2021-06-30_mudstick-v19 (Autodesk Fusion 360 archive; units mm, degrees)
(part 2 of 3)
sketch "Sketch19" plane through (2.9, 0, 0) normal (-1, 0, 0) x axis (0, -1, 0)
  line L1 (27.1, 161.9153) -> (13.5, 161.9153)
  line L2 (30.1, 117.9153) -> (30.1, 158.9153)
  line L3 (10.5, 114.9153) -> (27.1, 114.9153)
  line L4 (10.5, 114.75) -> (10.5, 114.9153)
  line L5 (10.1, 114.75) -> (10.5, 114.75)
  line L6 (10.1, 2.6653) -> (10.1, 114.75)
  line L7 (10.5, 2.6653) -> (10.1, 2.6653)
  line L8 (10.5, -11) -> (10.5, 2.6653)
  line L9 (27.35, -11) -> (10.5, -11)
  line L10 (27.35, -7.85) -> (27.35, -11)
  line L11 (52.65, -7.85) -> (27.35, -7.85)
  line L12 (52.65, -11) -> (52.65, -7.85)
  line L13 (73, -11) -> (52.65, -11)
  line L14 (73, 234.2448) -> (73, -11)
  line L15 (52.65, 234.2448) -> (73, 234.2448)
  line L16 (52.65, 231.0948) -> (52.65, 234.2448)
  line L17 (27.35, 231.0948) -> (52.65, 231.0948)
  line L18 (27.35, 234.2448) -> (27.35, 231.0948)
  line L19 (4, 234.2448) -> (27.35, 234.2448)
  line L20 (4, 182.2448) -> (4, 234.2448)
  line L21 (7.5, 179.2448) -> (7, 179.2448)
  line L22 (10.5, 164.9153) -> (10.5, 176.2448)
  line L23 (105.1, 16.4153) -> (85.1, 16.4153)
  line L24 (105.1, 36.4153) -> (105.1, 16.4153)
  line L25 (85.1, 36.4153) -> (105.1, 36.4153)
  line L26 (85.1, 16.4153) -> (85.1, 36.4153)
  line L27 (25, 7.4153) -> (65, 7.4153)
  line L28 (105.1, 26.4153) -> (85.1, 26.4153)
  arc A1 centre (13.5, 164.9153) radius 3 clockwise from (13.5, 161.9153) to (10.5, 164.9153)
  arc A2 centre (27.1, 158.9153) radius 3 clockwise from (27.1, 161.9153) to (30.1, 158.9153)
  arc A3 centre (27.1, 117.9153) radius 3 clockwise from (30.1, 117.9153) to (27.1, 114.9153)
  arc A4 centre (7, 182.2448) radius 3 clockwise from (7, 179.2448) to (4, 182.2448)
  arc A5 centre (7.5, 176.2448) radius 3 clockwise from (7.5, 179.2448) to (10.5, 176.2448)
  circle C1 centre (12, 224.2448) radius 2.125
  circle C2 centre (16.5, -5) radius 2.125
  circle C3 centre (63.5, -5) radius 2.125
  circle C4 centre (68, 224.2448) radius 2.125
  circle C5 centre (65, 7.4153) radius 1.65
  circle C6 centre (25, 7.4153) radius 1.65
  circle C7 centre (65, 45.4153) radius 1.65
  circle C8 centre (25, 45.4153) radius 1.65
  point P43 (65, 7.4153)
  point P45 (65, 7.4153)
  point P44 (25, 7.4153)
  point P46 (25, 7.4153)
  point P47 (85.1, 26.4153)
  point P48 (105.1, 26.4153)
  point P40 (105.1, 36.4153)
  point P41 (85.1, 36.4153)
  point P42 (0.1, 2.4153)
  horizontal L23
  vertical L24
  horizontal L25
  vertical L26
  equal L25 L26
  coincident P43 P45
  coincident P44 P46
  horizontal L27
  equal C5 C6
  midpoint L26 P47
  midpoint L24 P48
  symmetric C5 L28 C7
  symmetric C6 L28 C8
  dimension "d552" distance P40 P41 = 20
  dimension "d553" distance L23 P42 = 14
  dimension "d554" diameter C5 = 3.3
  dimension "d555" distance L23 L27 = 9
  dimension "d556" distance L14 P43 = 8
  dimension "d557" distance P45 P46 = 40
  dimension "d558" distance L26 P42 = 85
extrude "Extrude33" cut sketch "Sketch19" profile of C5 C6 C7 C8 to an object
fillet "Fillet23" radius 2
offset_faces "OffsetFaces1" distance -0.25
fillet "Fillet24" radius 2
fillet "Fillet25" radius 2
fillet "Fillet26" radius 3
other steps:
joint_origin "JointOrigin1"
joint_origin "JointOrigin2"
joint_origin "JointOrigin3"
named bodies: "Home Plate", "Canister", "Nozzle", "Drive", "Drive Cap", "Drive Housing", "Outer Plunger", "Ball Screw", "Inner Plunger", "Lower Cup", "West Wing", "East Wing", "Drive Housing (1)", "Handle"

design "PULL OUT DOWEL 6x16 97355A292"
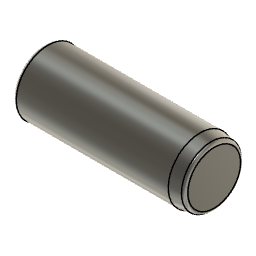
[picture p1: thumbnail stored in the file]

design "BHCS M4 x 25 92095A197"
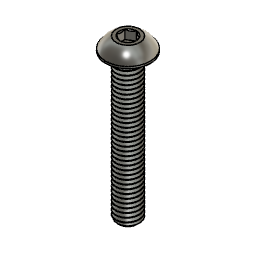
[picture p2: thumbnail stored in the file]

design "BHCS M4x10 92095A190"
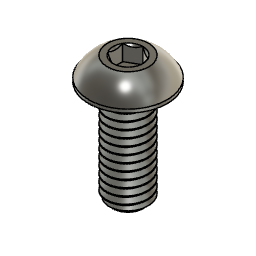
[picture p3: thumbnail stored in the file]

design "Mudstick Plate" references "Hotplate Pogo Drop", "BHCS M4 x 25 92095A197", "BHCS M4x10 92095A190", "PULL OUT DOWEL 6x16 97355A292"
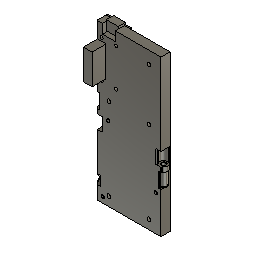
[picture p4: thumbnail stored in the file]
parameter "t_sheet_MAIN" = 7.9375 (= "5 / 16 * 1")
parameter "extrusion_w" = 20
parameter "extrusion_h" = 60
parameter "r_cutoutTool" = 2.05 (= "4.1 mm / 2")
parameter "od_bearings" = 13
parameter "id_bearings" = 4
parameter "t_bearings" = 5
parameter "preload" = 0.15
parameter "hw_m3_thru" = 3.5
parameter "hw_m3_thread" = 2.5
parameter "hw_m3_head" = 5.5
parameter "hw_m3_headheight" = 3
parameter "hw_m3_flathead" = 6
parameter "hw_m3_buttonhead" = 5.7
parameter "hw_m3_washer" = 7
parameter "hw_m3hex_d" = 5.5
parameter "hw_m3hex_t" = 4
parameter "hw_m3i_d" = 5.4
parameter "hw_m3i_l" = 3.8
parameter "hw_m3ichamfer" = 0.95 (= "( hw_m3i_d - hw_m3_thru ) / 2")
parameter "hw_m4_thru" = 4.25
parameter "hw_m4_head" = 7
parameter "hw_m4_headheight" = 4
parameter "hw_m4hex_d" = 7
parameter "hw_m4hex_t" = 5.2
parameter "hw_m4i_d" = 6
parameter "hw_m4i_l" = 4.8
parameter "hw_m4ichamfer" = 0.875 (= "( hw_m4i_d - hw_m4_thru ) / 2")
parameter "hw_m5_thread" = 4.2
parameter "hw_m5_head" = 8.5
parameter "hw_m5_washer" = 10
parameter "hw_m5_thru" = 5.25
parameter "hw_m6_thru" = 6.5
parameter "hw_m6_head" = 10
parameter "hw_m6_flathead" = 12
parameter "hw_m6_buttonhead" = 10.5
parameter "hw_m6_washer" = 12
parameter "p_belt" = 1.4
parameter "w_belt" = 10
parameter "t_belt" = 1.4
parameter "belt_pdo_toothside" = 1.15
parameter "belt_pdo_backside" = 0.25
parameter "t_m4_washer" = 0.85
parameter "flex_t" = 2.54
parameter "flex_l" = 5
parameter "t_motor_plates" = 6 comment "5/16 Phenolic"
parameter "swap_center_distance" = 40
parameter "pd_swap_drive" = 57.2958 (= "( nt_swap_drive * 2 / PI ) * 1 mm")
parameter "pd_swap_pinion" = 10.1859 (= "( nt_swap_pinion * 2 / PI ) * 1 mm")
parameter "od_mintool" = 2.1
parameter "t_sheet_THIN" = 5
parameter "c2c_spanners" = 14
parameter "c2c_height_pts" = 75
parameter "d954" = 1.7
parameter "d1221" = 5
parameter "d1747" = 9
parameter "d1748" = 5.5 (= "t_sheet_THIN + 0.5 mm")
parameter "d1761" = 2
parameter "d1917" = 5
sketch "Plan" plane through (0, 0, 0) normal (0, 0, 1) x axis (1, 0, 0)
  line L1 (-35, -5) -> (35, -5)
  line L2 (35, 5) -> (-35, 5)
  line L3 (35, -5) -> (35, 5)
  line L4 (-32.8378, -7.9826) -> (-38.2756, -10.5183)
  line L5 (-39.5997, 6.5183) -> (-32.8378, -7.9826)
  line L6 (-45.0375, 3.9826) -> (-39.5997, 6.5183)
  line L7 (-38.2756, -10.5183) -> (-45.0375, 3.9826)
  line L8 (-35.5567, -9.2505) -> (-42.3186, 5.2505)
  line L9 (-35, -3.8) -> (-35.5, -3.8)
  line L10 (-35, 3.8) -> (-35.5, 3.8)
  line L11 (-35.5, -3.8) -> (-35.5, 3.8)
  line L12 (-35.5, 0) -> (-35, 0)
  line L13 (0, -5) -> (0, 5)
  line L14 (35, 0) -> (-35, 0)
  line L15 (-33.25, 3) -> (-35, 3)
  line L16 (-30.25, -5) -> (-30.25, 0)
  line L17 (-32.75, -20) -> (-32.75, -12.9033)
  line L18 (-47.0948, -20) -> (-32.75, -20)
  line L19 (-58.5, 4.4586) -> (-47.0948, -20)
  line L20 (-58.5, 18.5) -> (-58.5, 4.4586)
  line L21 (-36.5156, 6.5) -> (0, 6.5)
  line L22 (-32.75, -12.9033) -> (-40.8544, 4.4768)
  line L23 (40, -5.1) -> (-40, -5.1)
  line L24 (40, -17.8) -> (40, -5.1)
  line L25 (-40, -17.8) -> (40, -17.8)
  line L26 (-40, -5.1) -> (-40, -17.8)
  line L27 (0, -17.8) -> (0, -5.1)
  line L28 (45, 18.5) -> (0, 18.5)
  line L29 (37.0839, 1.7621) -> (34.359, -5.7245)
  line L30 (39.0574, -7.4346) -> (34.359, -5.7245)
  line L31 (45.3388, -0.0273) -> (39.0574, -7.4346)
  line L32 (40, 4.5) -> (40, 24.5)
  line L33 (43.9547, 25.1) -> (46.9208, 5.55)
  line L34 (45, 4.5) -> (45, 18.5)
  line L35 (45, 4.5) -> (40, 4.5)
  line L36 (36, 6.5) -> (0, 6.5)
  line L37 (36, 4.5) -> (36, 6.5)
  line L38 (45, 0.5) -> (45, 4.5)
  line L39 (40, 0.5) -> (45, 0.5)
  line L40 (-58.5, 18.5) -> (0, 18.5)
  line L41 (0, 18.5) -> (0, 6.5)
  line L42 (-36.5156, 6.5) -> (-40.8544, 4.4768)
  line L43 (-35, 6.5) -> (-36.5156, 6.5)
  line L44 (-35, 18.5) -> (-35, 6.5)
  line L45 (35, 18.5) -> (35, 6.5)
  line L46 (40, 0.5) -> (36, 0.5)
  line L47 (40, 7.6754) -> (42.75, 6.0877)
  line L48 (37.25, 6.0877) -> (40, 7.6754)
  line L49 (37.25, 2.9123) -> (37.25, 6.0877)
  line L50 (40, 1.3246) -> (37.25, 2.9123)
  line L51 (42.75, 2.9123) -> (40, 1.3246)
  line L52 (42.75, 6.0877) -> (42.75, 2.9123)
  line L53 (43.1754, 24.5) -> (41.5877, 21.75)
  line L54 (41.5877, 27.25) -> (43.1754, 24.5)
  line L55 (38.4123, 27.25) -> (41.5877, 27.25)
  line L56 (36.8246, 24.5) -> (38.4123, 27.25)
  line L57 (38.4123, 21.75) -> (36.8246, 24.5)
  line L58 (41.5877, 21.75) -> (38.4123, 21.75)
  line L59 (36, 24.5) -> (36, 6.5)
  line L60 (36, 4.5) -> (36, 0.5)
  line L61 (20.3431, 18.5) -> (32.3431, 6.5)
  line L62 (-15, 11.5) -> (-35, 11.5)
  line L63 (-15, 18.5) -> (-15, 11.5)
  line L64 (-35, 2.4367) -> (-35, -5)
  line L65 (-35, 5) -> (-35, 3)
  line L66 (-33.25, -5) -> (-33.25, -3)
  line L67 (33.25, 3) -> (35, 3)
  line L68 (30.25, -5) -> (30.25, 0)
  line L69 (33.25, -5) -> (33.25, -3)
  line L70 (-35, 3) -> (-35, 2.4367)
  arc A1 centre (-32.1029, 0) radius 5.0971 clockwise from (-35.5, -3.8) to (-35.5, 3.8)
  circle C1 centre (-33.25, 0) radius 3
  circle C2 centre (33.25, 0) radius 3
  circle C3 centre (40, 4.5) radius 1.625
  circle C4 centre (40, 24.5) radius 1.625
  circle C5 centre (40, 24.5) radius 4
  circle C6 centre (40, 4.5) radius 4
  arc A2 centre (40, 4.5) radius 7 clockwise from (46.9208, 5.55) to (45.3388, -0.0273)
  circle C7 centre (-33.25, 0) radius 4.25
  circle C8 centre (-33.25, 0) radius 2.125
  circle C9 centre (33.25, 0) radius 3
  circle C10 centre (33.25, 0) radius 2.125
  circle C11 centre (33.25, 0) radius 4.25
  point P10 (-42.3186, 5.2505)
  point P11 (-35.5567, -9.2505)
  point P15 (-35, -3.8)
  point P16 (-35, 3.8)
  point P14 (-35.5, -3.8)
  point P17 (-35.5, -3.8)
  point P19 (-35.5, 0)
  point P20 (-37.2, 0)
  point P21 (0, 5)
  point P22 (0, -5)
  point P1 (0, 0)
  point P24 (35, 0)
  point P23 (-33.25, 0)
  point P25 (-35, 3)
  point P26 (-30.25, -5)
  point P27 (-38.9377, -2)
  point P41 (0, -5.1)
  point P42 (0, -17.8)
  point P52 (40, 24.5)
  point P54 (40, 24.5)
  point P49 (37.0839, 1.7621)
  point P58 (45.3388, -0.0273)
  point P51 (45.3388, -0.0273)
  point P60 (43.9547, 25.1)
  point P61 (40, 28.5)
  point P56 (40, 4.5)
  point P63 (40, 4.5)
  point P62 (45, 4.5)
  point P64 (45, 4.5)
  point P66 (36, 4.5)
  point P68 (40, 0.5)
  point P36 (0, 6.5)
  point P45 (0, 6.5)
  point P33 (-58.5, 18.5)
  point P69 (-58.5, 18.5)
  point P34 (-36.5156, 6.5)
  point P70 (-36.5156, 6.5)
  point P28 (-32.75, -12.9033)
  point P29 (-32.75, -12.9033)
  point P72 (-35, 18.5)
  point P4 (-35, 5)
  point P73 (35, 6.5)
  point P74 (35, 18.5)
  point P5 (35, 5)
  point P76 (40, 0.5)
  point P47 (40, 4.5)
  point P83 (40, 4.5)
  point P90 (40, 24.5)
  point P57 (40, 4.5)
  point P55 (40, 4.5)
  point P91 (36, 24.5)
  point P92 (36, 4.5)
  point P93 (32.3431, 6.5)
  point P94 (20.3431, 18.5)
  point P95 (-35, 11.5)
  point P97 (-15, 18.5)
  point P100 (-35, 2.4367)
  point P18 (-35, 0)
  point P101 (-33.25, 3)
  point P102 (-33.25, -3)
  point P103 (-33.25, -5)
  point P98 (-33.25, 0)
  point P104 (-30.25, 0)
  point P107 (35, 3)
  point P111 (30.25, -5)
  point P108 (33.25, 3)
  point P112 (33.25, -3)
  point P113 (33.25, -5)
  point P110 (30.25, 0)
  point P3 (-35, -5)
  point P6 (-38.2756, -10.5183)
  point P9 (-45.0375, 3.9826)
  point P8 (-39.5997, 6.5183)
  point P13 (-35.5, 3.8)
  point P37 (-40, -5.1)
  point P38 (40, -5.1)
  point P44 (33.25, 0)
  point P48 (34.359, -5.7245)
  point P50 (39.0574, -7.4346)
  point P53 (40, 24.5)
  point P67 (45, 0.5)
  point P43 (0, 18.5)
  point P79 (37.25, 6.0877)
  point P86 (41.5877, 27.25)
  point P96 (-15, 11.5)
  point P71 (-35, 6.5)
  horizontal L1
  vertical L64
  horizontal L2
  vertical L3
  perpendicular L4 L5
  parallel L4 L6
  parallel L5 L7
  midpoint L6 P10
  midpoint L4 P11
  coincident P15 L64
  perpendicular L9 L64
  coincident P16 L64
  perpendicular L10 L64
  perpendicular L10 L11
  coincident P14 P17
  perpendicular L12 L64
  midpoint L11 P19
  midpoint A1 P20
  midpoint L2 P21
  midpoint L1 P22
  midpoint P1 L13
  midpoint L3 P24
  coincident P23 L14
  coincident P25 L64
  perpendicular L15 L64
  coincident L1 P26
  perpendicular L1 L16
  midpoint L8 P27
  vertical L17
  perpendicular L17 L18
  vertical L20
  horizontal L23
  vertical L24
  horizontal L25
  vertical L26
  midpoint L23 P41
  midpoint L25 P42
  coincident P1 L27
  horizontal L21
  symmetric L13 C1 C2
  perpendicular L29 L30
  concentric C4 C5
  coincident P52 P54
  tangent C2 L29
  vertical L32
  coincident P49 C6
  coincident L31 P58
  coincident P51 P58
  tangent L31 A2
  coincident C5 P60
  tangent C5 L33
  tangent A2 L33
  coincident C5 P61
  coincident L32 P61
  perpendicular L28 L34
  coincident P56 P63
  perpendicular L32 L35
  coincident P62 P64
  perpendicular L36 L37
  coincident C6 P66
  coincident L35 P66
  perpendicular L35 L38
  perpendicular L34 L39
  coincident C6 P68
  coincident L32 P68
  coincident P36 P45
  coincident P33 P69
  perpendicular L28 L41
  coincident P1 L41
  horizontal L28
  horizontal L36
  horizontal L40
  perpendicular L5 L42
  coincident P34 P70
  parallel L8 L22
  coincident P28 P29
  parallel L8 L19
  parallel L21 L43
  coincident L40 P72
  perpendicular L40 L44
  coincident P4 L44
  coincident L36 P73
  coincident L28 P74
  perpendicular L28 L45
  coincident P5 L45
  equal C5 C6
  perpendicular L37 L46
  coincident P68 P76
  coincident P47 P83
  vertical L52
  coincident P52 P90
  horizontal L58
  coincident P57 P83
  coincident P55 P57
  coincident P47 P56
  coincident C5 P91
  perpendicular L46 L60
  coincident P66 P92
  coincident L36 P93
  coincident L28 P94
  tangent C6 L61
  coincident L44 P95
  perpendicular L41 L62
  coincident L40 P97
  perpendicular L40 L63
  tangent L5 C1
  concentric C1 C7
  concentric C1 C8
  coincident C1 P100
  collinear L64 L65
  coincident P18 L64
  coincident C1 P101
  coincident C1 P102
  coincident L1 P103
  perpendicular L1 L66
  coincident P98 L66
  coincident C1 P104
  symmetric L13 C1 C9
  symmetric L13 P25 P107
  symmetric L13 P26 P111
  symmetric L13 C7 C11
  symmetric L13 C8 C10
  symmetric L13 P101 P108
  symmetric L13 P102 P112
  symmetric L13 P103 P113
  symmetric L13 P104 P110
  dimension "d1706" distance P3 P4 = 10
  dimension "d1707" distance P6 P9 = 16
  dimension "d1708" distance P8 P9 = 6
  dimension "d1709" distance P13 P17 = 7.6
  dimension "d1710" distance P20 L64 = 2.2
  dimension "d1711" distance P13 P16 = 0.5
  dimension "d1712" distance P1 L64 = 35
  dimension "d1713" diameter C1 = 6
  dimension "d1714" distance P23 L64 = 1.75
  dimension "d1715" distance P23 L16 = 3 (= "d1713 / 2")
  dimension "d1716" distance P23 L15 = 3 (= "d1715")
  dimension "d1717" angle L8 L64 = 25
  dimension "d1723" distance L14 P27 = 2
  dimension "d1731" distance L17 L64 = 2.25
  dimension "d1732" distance L14 L18 = 20
  dimension "d1734" distance P27 L22 = 1
  dimension "d1763" distance P37 P38 = 80
  dimension "d1764" distance P41 P42 = 12.7
  dimension "d1765" distance L1 L23 = 0.1
  dimension "d1796" diameter C3 = 3.25
  dimension "d1799" distance L3 P47 = 5
  dimension "d1800" diameter C4 = 3.25
  dimension "d1802" angle L3 L29 = 20
  dimension "d1803" distance P44 L30 = 5
  dimension "d1804" distance P48 P50 = 5
  dimension "d1805" = 8.2688
  dimension "d1806" distance P47 P53 = 20
  dimension "d1808" = 1.5
  dimension "d1809" diameter C6 = 8
  dimension "d1810" distance P44 P47 = 4.5
  dimension "d1811" radius A2 = 7
  dimension "d1827" distance P67 P68 = 5
  dimension "d1955" distance L14 L21 = 6.5
  dimension "d1988" distance P36 P43 = 12
  dimension "d1989" distance P4 L42 = 2
  dimension "d1990" distance P27 L19 = 15
  dimension "d2035" distance P79 L52 = 5.5
  dimension "d2036" distance P86 L58 = 5.5
  dimension "d2063" angle L32 L61 = 45
  dimension "d2100" distance P95 P96 = 20
  dimension "d2126" distance P71 L62 = 5
  dimension "d2129" diameter C7 = 8.5
  dimension "d2130" diameter C8 = 4.25
  dimension "d2131" radius A1 = 5.0971
  dimension "d2236" distance L20 P72 = 23.5
  dimension "d523" OffsetX = 0
  dimension "d524" OffsetY = 0
  dimension "d525" OffsetZ = 0
  dimension "d526" AngleZ = 0
  dimension "d567" OffsetX = 0
  dimension "d568" OffsetY = 0
  dimension "d569" OffsetZ = 0
  dimension "d570" AngleZ = 0
  dimension "d1892" alignAngle = 180
  dimension "d1893" alignOffsetX = 0
  dimension "d1894" alignOffsetY = 0
  dimension "d1895" alignOffsetZ = 1
  dimension "d1896" radius = 1.05 (= "od_mintool / 2")
  dimension "d1897" distance = 1.05 (= "d1896")
  dimension "d1898" radius = 1.05 (= "od_mintool / 2")
  dimension "d1899" distance = 1.05 (= "d1898")
  dimension "d1900" distance = 17
  dimension "d1901" distance = 15
  dimension "d1916" distance = 10
  dimension "d1918" distance = 5
  dimension "d1919" distance = 25
  dimension "d1923" angle = 45
  dimension "d1924" diameter = 2.1 (= "od_mintool")
  dimension "d1925" diameter = 2.1 (= "od_mintool")
  dimension "d1926" diameter = 2.1 (= "od_mintool")
  dimension "d1932" angle = 45
  dimension "d1933" diameter = 2.1 (= "od_mintool")
  dimension "d1934" diameter = 2.1 (= "od_mintool")
  dimension "d1966" distance = 67
  dimension "d1967" distance = 33
  dimension "d1968" diameter = 2.5
  dimension "d1969" distance = 4
  dimension "d1970" distance = 29
  dimension "d1971" distance = 34
  dimension "d1972" distance = 54
  dimension "d1973" distance = 4
  dimension "d1974" distance = 3
  dimension "d1975" distance = 3
  dimension "d1976" distance = 5
  dimension "d1977" distance = 5
  dimension "d1978" distance = 1
  dimension "d1979" distance = 1
  dimension "d1980" distance = 10
  dimension "d1981" distance = 10
  dimension "d1982" distance = 6
  dimension "d1597" distance = 1.6
  dimension "d1598" distance = 67
  dimension "d1599" diameter = 4.25
  dimension "d1600" diameter = 3.3
  dimension "d1601" distance = 1
  dimension "d1602" distance = 1
  dimension "d1603" distance = 0.5
  dimension "d1604" distance = 12
  dimension "d1605" distance = 0.25
  dimension "d1606" distance = 0.25
  dimension "d1607" distance = 1
  dimension "d1608" distance = 8
  dimension "d1609" distance = 4.5
  dimension "d1610" distance = 4.5
  dimension "d1612" TaperAngle = 0
  dimension "d1613" AlongDistance = -53 (= "-20 mm - 33 mm")
  dimension "d1614" TaperAngle = 0
  dimension "d1615" ProfileOffset = 0.1
  dimension "d1616" Side1Offset = 0
  dimension "d1617" TaperAngle = 0
  dimension "d1618" leftDistance = 1
  dimension "d1619" distance = 67
  dimension "d1620" distance = 33
  dimension "d1621" distance = 0.5
  dimension "d1622" distance = 24.5
  dimension "d1623" diameter = 2.5
  dimension "d1624" distance = 4
  dimension "d1625" distance = 34
  dimension "d1626" distance = 54
  dimension "d1627" distance = 4
  dimension "d1628" distance = 29
  dimension "d1631" distance = 1
  dimension "d1633" distance = 3
  dimension "d1634" distance = 2.44 (= "d1643")
  dimension "d1635" diameter = 4
  dimension "d1636" distance = 15
  dimension "d1637" distance = 3
  dimension "d1638" distance = 15
  dimension "d1639" distance = 2
  dimension "d1640" Side1Offset = 0
  dimension "d1641" TaperAngle = 0
  dimension "d1642" distance = 2.44
  dimension "d1643" distance = 2.44
  dimension "d1644" AlongDistance = -16
  dimension "d1645" TaperAngle = 0
  dimension "d1647" Radius = 1
  dimension "d1649" Radius = 1
  dimension "d1651" Radius = 5
  dimension "d1653" Radius = 1
  dimension "d1654" diameter = 12
  dimension "d1655" Side1Offset = 0
  dimension "d1656" TaperAngle = 0
  dimension "d1658" Radius = 2
  dimension "d1659" distance = 20
  dimension "d1660" distance = 5
  dimension "d1661" distance = 5
  dimension "d981" distance = 15 (= "( 30 / 2 ) * 1 mm")
  dimension "d982" distance = 8
  dimension "d983" distance = 1.5
  dimension "d984" distance = 0.3
  dimension "d985" distance = 4
  dimension "d987" distance = 1
  dimension "d988" distance = 7.5
  dimension "d989" distance = 5
  dimension "d990" distance = 0.5
  dimension "d991" AlongAngle = 60
  dimension "d992" AgainstAngle = 60
  dimension "d993" distance = 4
  dimension "d994" angle = 60
  dimension "d995" angle = 60 (= "d994")
  dimension "d1004" diameter = 6.5
  dimension "d1005" distance = 1.5
  dimension "d1006" AlongDistance = -10
  dimension "d1007" TaperAngle = 0
  dimension "d1008" Side1Offset = 0
  dimension "d1009" TaperAngle = 0
  dimension "d1010" ProfileOffset = 0
  dimension "d1011" AlongDistance = -0.5
  dimension "d1012" TaperAngle = 0
  dimension "d1013" AlongDistance = 2.5
  dimension "d1014" TaperAngle = 0
  dimension "d1015" leftDistance = 0.25
  dimension "d1017" Radius = 1
  dimension "d1019" TotalAngle = 360
  dimension "d1020" ProfileOffset = 0
  dimension "d1021" Side1Offset = 0
  dimension "d1022" TaperAngle = 0
  dimension "d1028" angle = 25
  dimension "d1029" ProfileOffset = 0
  dimension "d1030" Side1Offset = 0
  dimension "d1031" TaperAngle = 0
  dimension "d1032" ProfileOffset = 0
  dimension "d1034" TaperAngle = 0
  dimension "d1035" Side1Offset = 0
  dimension "d1036" distance = 3
  dimension "d1037" leftDistance = 3
  dimension "d1038" rightDistance = 17.25
  dimension "d1039" Side1Offset = 0
  dimension "d1040" TaperAngle = 0
  dimension "d1042" TotalAngle = 360
  dimension "d1043" Side1Offset = 0
  dimension "d1044" TaperAngle = 2
  dimension "d1045" angle = 1
  dimension "d1047" Side1Offset = 0
  dimension "d1048" TaperAngle = 0
  dimension "d1049" distance = -1 (= "0 mm - 1 mm")
  dimension "d1051" TotalAngle = 360
  dimension "d1053" angle = 43.731
  dimension "d1054" angle = 28 (= "d1055 - d1056")
  dimension "d1055" angle = 50 (= "d1028 * 2")
  dimension "d1056" angle = 22
  dimension "d1058" Radius = 2
  dimension "d1060" Radius = 2
  dimension "d1061" alignAngle = 0
  dimension "d1062" alignOffsetX = 0
  dimension "d1063" alignOffsetY = 0
  dimension "d1064" alignOffsetZ = 0
  dimension "d1082" distance = 0.8
  dimension "d1084" distance = 0.8
  dimension "d1085" distance = 1.2
  dimension "d1086" distance = 1.2
  dimension "d1087" distance = 0.1
  dimension "d1093" Radius = 0.5
  dimension "d1095" Radius = 0.5
  dimension "d1097" Radius = 2
  dimension "d1103" distance = 1.3
  dimension "d1105" TotalAngle = 360
  dimension "d1106" distance = 2.75 (= "hw_m3hex_d / 2")
  dimension "d1107" distance = 1.75 (= "hw_m3_thru / 2")
  dimension "d1108" angle = 45
  dimension "d1109" distance = 3.6
  dimension "d1110" distance = 20
  dimension "d1111" distance = 1.7
  dimension "d1112" AlongAngle = 360
  dimension "d1113" Side1Offset = 0
  dimension "d1114" TaperAngle = 0
  dimension "d1116" TotalAngle = 360
  dimension "d1118" Radius = 2
  dimension "d1120" distance = 3.175 (= "1 / 8 * 1")
  dimension "d1121" radius = 12
  dimension "d1123" radius = 6.5
  dimension "d1124" angle = 60
  dimension "d1126" distance = 2.8797 (= "13 / 64 * 1  / 2 + 0.3 mm")
  dimension "d1127" distance = 9.5563 (= "7 / 32 * 1  + 4 mm")
  dimension "d1128" AlongDistance = -6
  dimension "d1129" diameter = 3.475 (= "1 / 8 * 1  + 0.3 mm")
  dimension "d1130" diameter = 1.7875 (= "1 / 16 * 1  + 0.2 mm")
  dimension "d1141" TwistAngle = 0
  dimension "d1142" TaperAngle = 0
  dimension "d1143" angle = 51
  dimension "d1144" distance = 2.8797 (= "d1126")
  dimension "d1145" diameter = 1.7875 (= "1 / 16 * 1  + 0.2 mm")
  dimension "d1150" TwistAngle = 0
  dimension "d1151" TaperAngle = 0
  dimension "d1152" distance = 1.7875 (= "1 / 16 * 1  + 0.2 mm")
  dimension "d1153" Side1Offset = 0
  dimension "d1154" TaperAngle = 0
  dimension "d1155" AlongDistance = -4
  dimension "d1156" TaperAngle = 0
  dimension "d1157" diameter = 5.3594 (= "13 / 64 * 1  + 0.2 mm")
  dimension "d1158" AlongDistance = 1.5
  dimension "d1159" TaperAngle = 0
  dimension "d1164" TwistAngle = 0
  dimension "d1165" TaperAngle = 0
  dimension "d1167" mirrorStitchTolerance = 0.1
  dimension "d1169" Radius = 0.4
  dimension "d1170" distance = 11
  dimension "d1171" distance = 1.0938 (= "( 1 / 16 * 1  + 0.2 mm ) / 2 + 0.2 mm")
  dimension "d1172" distance = 1.7
  dimension "d1173" distance = 1.7
  dimension "d1174" Side1Offset = 0
  dimension "d1175" TaperAngle = 0
  dimension "d1176" Side2Offset = -1
  dimension "d1177" Side2TaperAngle = 0
  dimension "d1179" mirrorStitchTolerance = 0.1
  dimension "d1181" Radius = 0.5
  dimension "d1182" alignAngle = 0
  dimension "d1183" alignOffsetX = 0
  dimension "d1184" alignOffsetY = 0
  dimension "d1185" alignOffsetZ = 0
  dimension "d1186" leftDistance = 0.75
  dimension "d1187" rightDistance = 3
  dimension "d1189" Radius = 12
  dimension "d1191" Radius = 2
  dimension "d1193" Radius = 0.5
  dimension "d1195" Radius = 0.5
  dimension "d1197" Radius = 0.5
  dimension "d1198" alignAngle = 0
  dimension "d1199" alignOffsetX = 0
  dimension "d1200" alignOffsetY = 0
  dimension "d1201" alignOffsetZ = 0
  dimension "d1202" distance = 13.5
sketch "Elevation" plane through (0, 0, 0) normal (0, 1, 0) x axis (1, 0, 0)
  line L1 (35, 0) -> (-35, 0)
  line L2 (35, -115) -> (35, 0)
  line L3 (-35, -115) -> (35, -115)
  line L4 (-35, 0) -> (-35, -115)
  line L5 (35, -10.5) -> (-35, -10.5)
  line L6 (-35, -15.5) -> (35, -15.5)
  line L7 (35, -24.5) -> (-35, -24.5)
  line L8 (-35, -29.5) -> (35, -29.5)
  line L9 (35, -85.5) -> (-35, -85.5)
  line L10 (-35, -90.5) -> (35, -90.5)
  line L11 (35, -99.5) -> (-35, -99.5)
  line L12 (-35, -104.5) -> (35, -104.5)
  line L13 (35, -45) -> (-35, -45)
  line L14 (35, -50) -> (-35, -50)
  line L15 (0, -90.5) -> (0, -99.5)
  line L16 (0, -24.5) -> (0, -15.5)
  line L17 (-35, 0) -> (35, 0)
  line L18 (0, -29.5) -> (0, -45)
  line L19 (0, -24.5) -> (0, -29.5)
  line L20 (0, -10.5) -> (0, -15.5)
  line L21 (0, -85.5) -> (0, -90.5)
  line L22 (0, -104.5) -> (0, -99.5)
  line L23 (25, -95) -> (-30, -95)
  line L24 (25, -20) -> (25, -95)
  line L25 (-30, -20) -> (25, -20)
  line L26 (-30, -95) -> (-30, -20)
  line L27 (-35, -55.5) -> (35, -55.5)
  line L28 (35, -60.5) -> (-35, -60.5)
  line L29 (0, -60.5) -> (0, -55.5)
  line L30 (0, -55.5) -> (0, -50)
  line L31 (-35.5, -78) -> (-56.5, -78)
  line L32 (-35.5, -37) -> (-35.5, -78)
  line L33 (-56.5, -37) -> (-35.5, -37)
  line L34 (-41, -82.25) -> (-51, -82.25)
  line L35 (-41, -32.75) -> (-41, -82.25)
  line L36 (-51, -32.75) -> (-41, -32.75)
  line L37 (-51, -82.25) -> (-51, -32.75)
  line L38 (-46, -57.5) -> (-46, -82.25)
  line L39 (-35.5, -57.5) -> (-46, -57.5)
  line L40 (-56.5, -85.5) -> (-56.5, -78)
  line L41 (-35, -85.5) -> (-56.5, -85.5)
  line L42 (-56.5, -29.5) -> (-35, -29.5)
  line L43 (-56.5, -37) -> (-56.5, -29.5)
  line L44 (-47.8246, -82.25) -> (-49.4123, -85)
  line L45 (-49.4123, -79.5) -> (-47.8246, -82.25)
  line L46 (-52.5877, -79.5) -> (-49.4123, -79.5)
  line L47 (-54.1754, -82.25) -> (-52.5877, -79.5)
  line L48 (-52.5877, -85) -> (-54.1754, -82.25)
  line L49 (-49.4123, -85) -> (-52.5877, -85)
  line L50 (-44.1754, -82.25) -> (-42.5877, -79.5)
  line L51 (-42.5877, -85) -> (-44.1754, -82.25)
  line L52 (-39.4123, -85) -> (-42.5877, -85)
  line L53 (-37.8246, -82.25) -> (-39.4123, -85)
  line L54 (-39.4123, -79.5) -> (-37.8246, -82.25)
  line L55 (-42.5877, -79.5) -> (-39.4123, -79.5)
  line L56 (-37.8246, -32.75) -> (-39.4123, -30)
  line L57 (-39.4123, -35.5) -> (-37.8246, -32.75)
  line L58 (-42.5877, -35.5) -> (-39.4123, -35.5)
  line L59 (-44.1754, -32.75) -> (-42.5877, -35.5)
  line L60 (-39.4123, -30) -> (-42.5877, -30)
  line L61 (-42.5877, -30) -> (-44.1754, -32.75)
  line L62 (-52.5877, -35.5) -> (-49.4123, -35.5)
  line L63 (-54.1754, -32.75) -> (-52.5877, -35.5)
  line L64 (-52.5877, -30) -> (-54.1754, -32.75)
  line L65 (-49.4123, -30) -> (-52.5877, -30)
  line L66 (-49.4123, -35.5) -> (-47.8246, -32.75)
  line L67 (-47.8246, -32.75) -> (-49.4123, -30)
  line L68 (-47, -80.75) -> (-47, -78)
  line L69 (-45, -78) -> (-45, -80.75)
  line L70 (-46, -80.75) -> (-46, -78)
  line L71 (-47, -34.25) -> (-47, -37)
  line L72 (-45, -37) -> (-45, -34.25)
  circle C1 centre (-51, -82.25) radius 1.625
  circle C2 centre (-41, -82.25) radius 1.625
  circle C3 centre (-41, -32.75) radius 1.625
  circle C4 centre (-51, -32.75) radius 1.625
  arc A1 centre (-46, -80.75) radius 1 clockwise from (-45, -80.75) to (-47, -80.75)
  arc A2 centre (-46, -78) radius 1 clockwise from (-47, -78) to (-45, -78)
  arc A3 centre (-46, -34.25) radius 1 clockwise from (-47, -34.25) to (-45, -34.25)
  arc A4 centre (-46, -37) radius 1 clockwise from (-45, -37) to (-47, -37)
  circle C5 centre (-23, -81) radius 1.65
  circle C6 centre (-23, -81) radius 4
  circle C7 centre (-29, -6) radius 1.65
  circle C8 centre (-29, -6) radius 4
  circle C9 centre (29, -38.75) radius 1.65
  circle C10 centre (29, -38.75) radius 4
  point P2 (35, 0)
  point P7 (-35, -10.5)
  point P8 (35, -10.5)
  point P9 (35, -15.5)
  point P10 (-35, -15.5)
  point P11 (-35, -24.5)
  point P12 (35, -24.5)
  point P13 (35, -29.5)
  point P14 (-35, -29.5)
  point P15 (-35, -85.5)
  point P16 (35, -85.5)
  point P17 (35, -90.5)
  point P18 (-35, -90.5)
  point P19 (-35, -99.5)
  point P20 (35, -99.5)
  point P21 (35, -104.5)
  point P22 (-35, -104.5)
  point P23 (-35, -45)
  point P24 (35, -45)
  point P25 (-35, -50)
  point P26 (35, -50)
  point P27 (0, -99.5)
  point P28 (0, -90.5)
  point P29 (0, -15.5)
  point P30 (0, -24.5)
  point P31 (0, -95)
  point P32 (0, -20)
  point P35 (0, -45)
  point P36 (0, -29.5)
  point P37 (0, -37.25)
  point P38 (0, -10.5)
  point P39 (0, -85.5)
  point P40 (0, -104.5)
  point P41 (0, -102)
  point P42 (0, -88)
  point P43 (0, -27)
  point P44 (0, -13)
  point P1 (0, 0)
  point P49 (0, 0)
  point P50 (35, -55.5)
  point P51 (-35, -55.5)
  point P52 (-35, -60.5)
  point P53 (35, -60.5)
  point P54 (0, -55.5)
  point P55 (0, -60.5)
  point P56 (0, -58)
  point P57 (0, -50)
  point P58 (0, -52.75)
  point P67 (-46, -82.25)
  point P70 (-41, -57.5)
  point P69 (-35.5, -57.5)
  point P71 (-46, -78)
  point P73 (-35, -85.5)
  point P62 (-56.5, -37)
  point P75 (-56.5, -37)
  point P63 (-51, -82.25)
  point P76 (-51, -82.25)
  point P64 (-41, -82.25)
  point P77 (-41, -82.25)
  point P84 (-51, -82.25)
  point P91 (-41, -82.25)
  point P78 (-49.4123, -85)
  point P103 (-49.4123, -30)
  point P79 (-47.8246, -82.25)
  point P104 (-47.8246, -32.75)
  point P80 (-49.4123, -79.5)
  point P99 (-49.4123, -35.5)
  point P81 (-52.5877, -79.5)
  point P100 (-52.5877, -35.5)
  point P82 (-54.1754, -82.25)
  point P101 (-54.1754, -32.75)
  point P83 (-52.5877, -85)
  point P102 (-52.5877, -30)
  point P85 (-42.5877, -79.5)
  point P96 (-42.5877, -35.5)
  point P86 (-44.1754, -82.25)
  point P97 (-44.1754, -32.75)
  point P87 (-42.5877, -85)
  point P98 (-42.5877, -30)
  point P88 (-39.4123, -85)
  point P93 (-39.4123, -30)
  point P89 (-37.8246, -82.25)
  point P94 (-37.8246, -32.75)
  point P90 (-39.4123, -79.5)
  point P95 (-39.4123, -35.5)
  point P111 (-46, -80.75)
  point P110 (-46, -78)
  point P106 (-47, -78)
  point P112 (-47, -37)
  point P107 (-47, -80.75)
  point P113 (-47, -34.25)
  point P108 (-45, -80.75)
  point P115 (-45, -34.25)
  point P109 (-45, -78)
  point P116 (-45, -37)
  point P118 (-35, 0)
  point P34 (-35, 0)
  point P59 (-56.5, -78)
  point P60 (-35.5, -78)
  point P61 (-35.5, -37)
  point P66 (-51, -32.75)
  point P121 (-29, -6)
  point P119 (-23, -81)
  point P123 (29, -38.75)
  point P4 (35, 0)
  point P5 (35, -115)
  point P6 (-35, -115)
  horizontal L1
  vertical L2
  horizontal L3
  vertical L4
  coincident P2 L2
  coincident L4 P7
  coincident L2 P8
  perpendicular L2 L5
  coincident L2 P9
  coincident L4 P10
  perpendicular L4 L6
  coincident L4 P11
  coincident L2 P12
  perpendicular L4 L7
  coincident L2 P13
  coincident L4 P14
  perpendicular L4 L8
  coincident L4 P15
  coincident L2 P16
  perpendicular L2 L9
  coincident L2 P17
  coincident L4 P18
  perpendicular L4 L10
  coincident L4 P19
  coincident L2 P20
  perpendicular L2 L11
  coincident L2 P21
  coincident L4 P22
  perpendicular L4 L12
  coincident L4 P23
  coincident L2 P24
  perpendicular L2 L13
  coincident L4 P25
  coincident L2 P26
  perpendicular L2 L14
  midpoint L11 P27
  midpoint L10 P28
  midpoint L6 P29
  perpendicular L6 L16
  coincident L7 P30
  midpoint L15 P31
  midpoint L16 P32
  midpoint L13 P35
  midpoint L8 P36
  midpoint L18 P37
  midpoint L5 P38
  midpoint L9 P39
  midpoint L12 P40
  midpoint L22 P41
  midpoint L21 P42
  midpoint L19 P43
  midpoint L20 P44
  horizontal L23
  vertical L24
  horizontal L25
  vertical L26
  coincident P32 L25
  coincident P31 L23
  coincident P1 P49
  coincident L2 P50
  coincident L4 P51
  perpendicular L4 L27
  coincident L4 P52
  coincident L2 P53
  perpendicular L2 L28
  midpoint L27 P54
  midpoint L28 P55
  midpoint L29 P56
  midpoint L14 P57
  midpoint L30 P58
  horizontal L31
  perpendicular L31 L32
  perpendicular L32 L33
  horizontal L34
  vertical L35
  horizontal L36
  vertical L37
  midpoint L34 P67
  perpendicular L31 L38
  perpendicular L38 L39
  midpoint L35 P70
  coincident L39 P70
  midpoint L32 P69
  midpoint L31 P71
  coincident L38 P71
  perpendicular L31 L40
  coincident L4 P73
  perpendicular L4 L41
  coincident P15 L41
  perpendicular L4 L42
  perpendicular L42 L43
  coincident P62 P75
  coincident L40 P75
  equal L40 L43
  coincident P63 P76
  coincident P64 P77
  equal C1 C2
  coincident P76 P84
  horizontal L49
  coincident P77 P91
  horizontal L52
  equal L49 L52
  symmetric L39 C1 C4
  symmetric L39 C2 C3
  symmetric L39 P78 P103
  symmetric L39 P79 P104
  symmetric L39 P80 P99
  symmetric L39 P81 P100
  symmetric L39 P82 P101
  symmetric L39 P83 P102
  symmetric L39 P85 P96
  symmetric L39 P86 P97
  symmetric L39 P87 P98
  symmetric L39 P88 P93
  symmetric L39 P89 P94
  symmetric L39 P90 P95
  tangent L68 A1
  tangent A1 L69
  parallel L68 L69
  tangent L69 A2
  tangent L68 A2
  coincident L38 P111
  perpendicular L31 L70
  coincident P71 P110
  symmetric L39 P106 P112
  symmetric L39 P107 P113
  symmetric L39 P108 P115
  symmetric L39 P109 P116
  symmetric L39 A1 A3
  symmetric L39 A2 A4
  coincident L4 P118
  coincident L1 P34
  concentric C5 C6
  concentric C7 C8
  concentric C9 C10
  dimension "d1742" distance L7 L8 = 5 (= "t_sheet_THIN")
  dimension "d1743" distance L5 L6 = 5 (= "t_sheet_THIN")
  dimension "d1744" distance L13 L14 = 5 (= "t_sheet_THIN")
  dimension "d1745" distance L9 L10 = 5 (= "t_sheet_THIN")
  dimension "d1746" distance L11 L12 = 5 (= "t_sheet_THIN")
  dimension "d1750" distance P32 L17 = 20
  dimension "d1751" distance P31 P32 = 75 (= "c2c_height_pts")
  dimension "d1752" distance L17 P37 = 37.25
  dimension "d1789" distance P43 P44 = 14 (= "c2c_spanners")
  dimension "d1791" distance P41 P42 = 14 (= "c2c_spanners")
  dimension "d1945" distance P31 L24 = 25
  dimension "d1946" distance P31 L26 = 30
  dimension "d1956" distance P54 P55 = 5 (= "t_sheet_THIN")
  dimension "d1957" distance L14 L27 = 5.5 (= "d1748")
  dimension "d2014" distance P59 P60 = 21
  dimension "d2015" distance P60 P61 = 41
  dimension "d2016" distance P63 P66 = 49.5
  dimension "d2017" distance P63 P64 = 10
  dimension "d2019" diameter C1 = 3.25
  dimension "d2020" distance P81 L49 = 5.5
  dimension "d2021" distance P107 L69 = 2
  dimension "d2022" distance L34 P111 = 1.5
  dimension "d2030" distance L4 L32 = 0.5
  dimension "d2031" distance L30 P62 = 56.5
  dimension "d2223" diameter C6 = 8
  dimension "d2224" diameter C5 = 3.3
  dimension "d2207" diameter C8 = 8
  dimension "d2208" diameter C7 = 3.3
  dimension "d2209" diameter C10 = 8
  dimension "d2210" diameter C9 = 3.3
  dimension "d2211" distance L4 P121 = 6
  dimension "d2212" distance L25 P121 = 14
  dimension "d2214" distance L4 P119 = 12
  dimension "d2216" distance L2 P123 = 6
  dimension "d2237" distance L3 P31 = 20 (= "d1750")
  dimension "d2238" distance P4 P5 = 115
  dimension "d2239" distance P5 P6 = 70
  dimension "d2241" distance P32 P58 = 32.75
  dimension "d2242" distance P58 P123 = 14
  dimension "d2243" distance P31 P119 = 14
  dimension "d1938" diameter = 4.25
  dimension "d1940" diameter = 8
extrude "Extrude198" new body sketch "Plan" profile of L1 L65 L2 L3 C1 L15 L16 L29 C7 C8 L66 C9 C10 L67 C11 L68 L69 L70 to an object
extrude "Extrude199" sketch "Plan" profile of L1 L65 C1 L15 C7 C8 L66 L70 blind 16.25
extrude "Extrude200" sketch "Plan" profile of L1 L3 L29 C9 C10 L67 C11 L69 blind 16.25
extrude "Extrude201" sketch "Plan" profile of L3 L29 C6 L46 L60 C9 C10 C11 blind 5
extrude "Extrude202" sketch "Plan" profile of L1 L3 L29 C6 L46 L60 C9 C10 L67 C11 L68 L69 blind 15
extrude "Extrude203" sketch "Plan" profile of L3 C10 to an object
extrude "Extrude204" sketch "Plan" profile of L65 C1 C7 C8 L70 blind -5
extrude "Extrude205" sketch "Plan" profile of L1 L65 C1 L15 L16 C7 C8 L66 L70 blind -15
extrude "Extrude206" sketch "Plan" profile of L65 C8 to an object
fillet "Fillet88" ChordLen 1
fillet "Fillet89" ChordLen 1
chamfer "Chamfer23" distance 0.5
fillet "Fillet90" ChordLen 1
fillet "Fillet91" ChordLen 1
sketch "Side Mount" plane through (-35, 0, 0) normal (-1, 0, 0) x axis (0, -1, 0)
  line L1 (-4.4874, 81.875) -> (-4.4874, 86.875)
  line L2 (-4.4874, 81.875) -> (-4.7601, 81.875)
  line L3 (-4.7601, 66.875) -> (-4.7601, 81.875)
  line L4 (-5, 115) -> (5, 115)
  line L5 (-5, 0) -> (-5, 115)
  line L6 (5, 0) -> (-5, 0)
  line L7 (5, 115) -> (5, 103.125)
  line L8 (-3.7071, 86.875) -> (-4.4874, 86.875)
  line L9 (-3.7071, 86.875) -> (-3.7071, 103.125)
  line L10 (5, 103.125) -> (-3.7071, 103.125)
  line L11 (0, 24.45) -> (0, 15.55)
  line L12 (4.0415, 24.45) -> (2.0207, 20.95)
  line L13 (2.0207, 27.95) -> (4.0415, 24.45)
  line L14 (-2.0207, 27.95) -> (2.0207, 27.95)
  line L15 (-4.0415, 24.45) -> (-2.0207, 27.95)
  line L16 (-2.0207, 20.95) -> (-4.0415, 24.45)
  line L17 (2.0207, 20.95) -> (-2.0207, 20.95)
  line L18 (-4.0415, 15.55) -> (-2.0207, 19.05)
  line L19 (4.0415, 15.55) -> (2.0207, 12.05)
  line L20 (2.0207, 12.05) -> (-2.0207, 12.05)
  line L21 (2.0207, 19.05) -> (4.0415, 15.55)
  line L22 (-2.0207, 19.05) -> (2.0207, 19.05)
  line L23 (-2.0207, 12.05) -> (-4.0415, 15.55)
  line L24 (-2.8868, 28.45) -> (-2.0207, 27.95)
  line L25 (-5, 28.45) -> (-2.8868, 28.45)
  line L26 (-2.8868, 20.45) -> (-2.0207, 20.95)
  line L27 (-5, 20.45) -> (-2.8868, 20.45)
  line L28 (-5, 20) -> (0, 20)
  line L29 (-2.8868, 19.55) -> (-2.0207, 19.05)
  line L30 (-5, 19.55) -> (-2.8868, 19.55)
  line L31 (-2.8868, 11.55) -> (-2.0207, 12.05)
  line L32 (-5, 11.55) -> (-2.8868, 11.55)
  line L33 (2, 20) -> (5, 25.1962)
  line L34 (5, 14.8038) -> (2, 20)
  line L35 (5, 66.875) -> (5, 0)
  line L36 (-4.7601, 66.875) -> (5, 66.875)
  circle C1 centre (0, 24.45) radius 1.7
  circle C2 centre (0, 15.55) radius 1.7
  circle C3 centre (0, 24.45) radius 4
  circle C4 centre (0, 15.55) radius 4
  point P1 (0, 0)
  point P14 (0, 20)
  point P15 (0, 20)
  point P16 (0, 24.45)
  point P23 (0, 24.45)
  point P25 (0, 15.55)
  point P30 (0, 15.55)
  point P12 (0, 15.55)
  point P13 (0, 24.45)
  point P33 (0, 15.55)
  point P35 (-5, 28.45)
  point P37 (-5, 20.45)
  point P38 (0, 20)
  point P39 (-5, 20)
  point P20 (-2.0207, 27.95)
  point P43 (-2.0207, 12.05)
  point P22 (-2.0207, 20.95)
  point P40 (-2.0207, 19.05)
  point P34 (-2.8868, 28.45)
  point P44 (-2.8868, 11.55)
  point P45 (-5, 11.55)
  point P36 (-2.8868, 20.45)
  point P41 (-2.8868, 19.55)
  point P42 (-5, 19.55)
  point P46 (5, 25.1962)
  point P48 (5, 14.8038)
  point P47 (2, 20)
  point P19 (2.0207, 27.95)
  point P26 (2.0207, 19.05)
  point P32 (0, 24.45)
  vertical L11
  coincident P1 L11
  midpoint L11 P14
  coincident P14 P15
  coincident P16 P23
  coincident P25 P30
  horizontal L14
  horizontal L22
  coincident P12 P30
  coincident P13 P23
  concentric C1 C3
  coincident P25 P33
  equal C3 C4
  perpendicular L15 L24
  coincident L5 P35
  perpendicular L5 L25
  perpendicular L16 L26
  coincident L5 P37
  perpendicular L5 L27
  coincident P15 P38
  coincident L5 P39
  perpendicular L5 L28
  symmetric P20 L28 P43
  symmetric P22 L28 P40
  symmetric P34 L28 P44
  symmetric P35 L28 P45
  symmetric P36 L28 P41
  symmetric P37 L28 P42
  coincident L7 P46
  coincident L7 P48
  coincident L28 P47
  dimension "d2167" distance P19 L17 = 7
  dimension "d2168" diameter C1 = 3.4
  dimension "d2169" distance P26 L20 = 7
  dimension "d2170" diameter C2 = 3.4 (= "d2168")
  dimension "d2171" distance P12 P13 = 8.9
  dimension "d2172" diameter C3 = 8
  dimension "d2173" distance L17 L22 = 1.9
  dimension "d2174" distance P32 L27 = 4
  dimension "d2175" distance P32 L25 = 4
  dimension "d2200" angle L28 L33 = 60
  dimension "d2201" distance L7 P47 = 3
  dimension "d2204" angle L28 L34 = 60 (= "d2200")
extrude "Extrude207" cut sketch "Side Mount" profile of C1 C2 against normal blind 12
chamfer "Chamfer24" distance 0.5
extrude "Extrude210" cut sketch "Side Mount" profile of L7 L33 L34 against normal blind 4
extrude "Extrude211" sketch "Elevation" profile of C5 C7 C9 to an object
sketch "Pogo Conn" plane through (0, 0, 0) normal (0, 1, 0) x axis (1, 0, 0)
  line L1 (-35, -110.5) -> (-9, -110.5)
  line L2 (-35, -170.5) -> (-35, -110.5)
  line L3 (-9, -170.5) -> (-35, -170.5)
  line L4 (-9, -110.5) -> (-9, -170.5)
  line L5 (-19.5, -159.25) -> (-24.5, -159.25)
  line L6 (-19.5, -112.75) -> (-19.5, -159.25)
  line L7 (-24.5, -112.75) -> (-19.5, -112.75)
  line L8 (-24.5, -159.25) -> (-24.5, -112.75)
  line L9 (-19.5, -112.75) -> (-24.5, -159.25)
  line L10 (-19.5, -159.25) -> (-24.5, -112.75)
  line L11 (-14, -156.5) -> (-30, -156.5)
  line L12 (-14, -115.5) -> (-14, -156.5)
  line L13 (-30, -115.5) -> (-14, -115.5)
  line L14 (-30, -156.5) -> (-30, -115.5)
  line L15 (-25.5, -153) -> (-35, -153)
  line L16 (-25.5, -119) -> (-25.5, -153)
  line L17 (-35, -119) -> (-25.5, -119)
  line L18 (-25.5, -136) -> (-22, -136)
  line L19 (-15, -172.5) -> (-29, -172.5)
  line L20 (-15, -160.25) -> (-15, -172.5)
  line L21 (-29, -160.25) -> (-15, -160.25)
  line L22 (-29, -172.5) -> (-29, -160.25)
  line L23 (-22, -160.25) -> (-22, -136)
  circle C1 centre (-30, -156.5) radius 1.7
  circle C2 centre (-30, -115.5) radius 1.7
  circle C3 centre (-14, -156.5) radius 1.7
  circle C4 centre (-14, -115.5) radius 1.7
  point P10 (-22, -136)
  point P14 (-14, -115.5)
  point P17 (-14, -115.5)
  point P11 (-30, -156.5)
  point P15 (-30, -156.5)
  point P13 (-14, -156.5)
  point P16 (-14, -156.5)
  point P12 (-30, -115.5)
  point P18 (-30, -115.5)
  point P19 (-35, -153)
  point P22 (-35, -119)
  point P23 (-22, -136)
  point P24 (-25.5, -136)
  point P29 (-22, -136)
  point P30 (-22, -160.25)
  point P4 (-35, -170.5)
  point P5 (-9, -170.5)
  point P3 (-35, -110.5)
  point P7 (-19.5, -159.25)
  point P8 (-19.5, -112.75)
  point P6 (-24.5, -159.25)
  point P1 (0, 0)
  point P2 (-9, -110.5)
  point P20 (-25.5, -153)
  point P21 (-25.5, -119)
  point P25 (-29, -172.5)
  point P26 (-15, -172.5)
  horizontal L1
  vertical L2
  horizontal L3
  vertical L4
  horizontal L5
  vertical L6
  horizontal L7
  vertical L8
  midpoint L10 P10
  equal C2 C4
  equal C1 C2
  equal C1 C3
  horizontal L11
  vertical L12
  horizontal L13
  vertical L14
  coincident P14 P17
  coincident P11 P15
  coincident P13 P16
  coincident P12 P18
  coincident L2 P19
  perpendicular L2 L15
  perpendicular L15 L16
  coincident L2 P22
  perpendicular L2 L17
  coincident P10 P23
  midpoint L16 P24
  horizontal L18
  horizontal L19
  vertical L20
  horizontal L21
  vertical L22
  coincident P10 P29
  midpoint L21 P30
  vertical L23
  dimension "d2245" distance P4 P5 = 26
  dimension "d2246" distance P3 P4 = 60
  dimension "d2247" distance L2 P10 = 13
  dimension "d2248" distance L1 P10 = 25.5
  dimension "d2249" distance P7 P8 = 46.5
  dimension "d2250" distance P6 P7 = 5
  dimension "d2251" distance P1 P10 = 136
  dimension "d2252" distance P1 P10 = 22
  dimension "d2253" diameter C1 = 3.4
  dimension "d2254" distance L2 L14 = 5
  dimension "d2255" distance L4 L12 = 5
  dimension "d2256" distance P2 L13 = 5
  dimension "d2257" distance L3 L11 = 14
  dimension "d2261" distance P20 P21 = 34
  dimension "d2262" distance P19 P20 = 9.5
  dimension "d2274" distance P25 P26 = 14
  dimension "d2275" distance L3 L19 = 2
  dimension "d2276" distance P7 L21 = 1
extrude "Extrude212" sketch "Pogo Conn" profile of L1 L2 L3 L4 C1 C2 C3 C4 L15 L16 L17 L20 L21 L22 to an object
extrude "Extrude214" sketch "Pogo Conn" profile of C2 C4 to an object
component_insert "Component Insert66"
joint "Assemble63" alignAngle 90 alignOffsetX 0 alignOffsetY 0 alignOffsetZ 0
sketch "Sketch60" plane through (0, 5, 0) normal (0, 1, 0) x axis (-1, 0, 0)
  line L1 (-35, 115) -> (9, 115)
  line L2 (-35, 0) -> (-35, 115)
  line L3 (35, 0) -> (-35, 0)
  line L4 (35, 119) -> (35, 0)
  line L5 (25.5, 119) -> (35, 119)
  line L6 (25.5, 153) -> (25.5, 119)
  line L7 (35, 153) -> (25.5, 153)
  line L8 (35, 170.5) -> (35, 153)
  line L9 (29, 170.5) -> (35, 170.5)
  line L10 (29, 160.25) -> (29, 170.5)
  line L11 (15, 160.25) -> (29, 160.25)
  line L12 (15, 170.5) -> (15, 160.25)
  line L13 (9, 170.5) -> (15, 170.5)
  line L14 (9, 115) -> (9, 170.5)
  line L15 (-22, 10) -> (22, 10)
  line L16 (-22, 100) -> (-22, 10)
  line L17 (22, 100) -> (-22, 100)
  line L18 (22, 10) -> (22, 100)
  line L19 (0, 0) -> (0, 10)
  line L20 (-17.9585, 10) -> (-19.9793, 6.5)
  line L21 (-19.9793, 13.5) -> (-17.9585, 10)
  line L22 (-24.0207, 13.5) -> (-19.9793, 13.5)
  line L23 (-26.0415, 10) -> (-24.0207, 13.5)
  line L24 (-24.0207, 6.5) -> (-26.0415, 10)
  line L25 (-19.9793, 6.5) -> (-24.0207, 6.5)
  line L26 (-26.0415, 100) -> (-24.0207, 103.5)
  line L27 (-19.9793, 103.5) -> (-17.9585, 100)
  line L28 (-24.0207, 96.5) -> (-26.0415, 100)
  line L29 (-24.0207, 103.5) -> (-19.9793, 103.5)
  line L30 (-17.9585, 100) -> (-19.9793, 96.5)
  line L31 (-19.9793, 96.5) -> (-24.0207, 96.5)
  line L32 (17.9585, 10) -> (19.9793, 13.5)
  line L33 (24.0207, 13.5) -> (26.0415, 10)
  line L34 (19.9793, 6.5) -> (17.9585, 10)
  line L35 (19.9793, 13.5) -> (24.0207, 13.5)
  line L36 (26.0415, 10) -> (24.0207, 6.5)
  line L37 (24.0207, 6.5) -> (19.9793, 6.5)
  line L38 (17.9585, 100) -> (19.9793, 103.5)
  line L39 (24.0207, 103.5) -> (26.0415, 100)
  line L40 (19.9793, 96.5) -> (17.9585, 100)
  line L41 (19.9793, 103.5) -> (24.0207, 103.5)
  line L42 (26.0415, 100) -> (24.0207, 96.5)
  line L43 (24.0207, 96.5) -> (19.9793, 96.5)
  line L44 (-22, 157) -> (-22, 100)
  line L45 (-24.0207, 160.5) -> (-19.9793, 160.5)
  line L46 (-17.9585, 157) -> (-19.9793, 153.5)
  line L47 (-19.9793, 160.5) -> (-17.9585, 157)
  line L48 (-26.0415, 157) -> (-24.0207, 160.5)
  line L49 (-19.9793, 153.5) -> (-24.0207, 153.5)
  line L50 (-24.0207, 153.5) -> (-26.0415, 157)
  line L51 (9, 170.5) -> (9, 115)
  line L52 (9, 115) -> (-35, 115)
  line L53 (-35, 170.5) -> (9, 170.5)
  line L54 (-35, 115) -> (-35, 170.5)
  circle C1 centre (14, 115.5) radius 1.7
  circle C2 centre (30, 115.5) radius 1.7
  circle C3 centre (14, 156.5) radius 1.7
  circle C4 centre (30, 156.5) radius 1.7
  circle C5 centre (23, 81) radius 1.65
  circle C6 centre (29, 6) radius 1.65
  circle C7 centre (-29, 38.75) radius 1.65
  circle C8 centre (-22, 10) radius 2.125
  circle C9 centre (-22, 100) radius 2.125
  circle C10 centre (22, 10) radius 2.125
  circle C11 centre (22, 100) radius 2.125
  circle C12 centre (-22, 157) radius 2.125
  point P27 (0, 10)
  point P1 (0, 0)
  point P28 (0, 0)
  point P29 (-22, 10)
  point P36 (-22, 10)
  point P43 (-22, 100)
  point P44 (-22, 100)
  point P51 (22, 10)
  point P52 (22, 10)
  point P59 (22, 100)
  point P60 (22, 100)
  point P24 (-22, 10)
  point P25 (-22, 100)
  point P26 (22, 100)
  point P23 (22, 10)
  point P61 (-22, 100)
  point P67 (-22, 157)
  point P72 (-22, 157)
  point P68 (-22, 157)
  point P63 (-22, 157)
  point P62 (-22, 157)
  point P74 (9, 170.5)
  point P76 (9, 170.5)
  point P5 (-35, 115)
  point P78 (-35, 115)
  point P33 (-24.0207, 13.5)
  point P37 (-24.0207, 103.5)
  point P45 (19.9793, 13.5)
  point P53 (19.9793, 103.5)
  point P65 (-24.0207, 160.5)
  horizontal L15
  vertical L16
  horizontal L17
  vertical L18
  midpoint L15 P27
  coincident P1 P28
  vertical L19
  coincident P29 P36
  horizontal L25
  coincident P43 P44
  horizontal L31
  coincident P51 P52
  horizontal L37
  coincident P59 P60
  horizontal L43
  coincident P24 P29
  coincident P25 P43
  coincident P26 P59
  coincident P23 P52
  coincident P43 P61
  perpendicular L29 L44
  coincident P67 P72
  horizontal L49
  coincident P68 P72
  coincident P63 P72
  coincident P62 P63
  coincident P74 P76
  perpendicular L51 L53
  perpendicular L13 L54
  coincident P5 P78
  dimension "d2277" distance P25 P26 = 44
  dimension "d2278" distance P24 P25 = 90
  dimension "d2279" distance P27 P28 = 10
  dimension "d2280" diameter C8 = 4.25
  dimension "d2281" distance P33 L25 = 7
  dimension "d2282" diameter C9 = 4.25
  dimension "d2283" distance P37 L31 = 7
  dimension "d2284" diameter C10 = 4.25
  dimension "d2285" distance P45 L37 = 7
  dimension "d2286" diameter C11 = 4.25
  dimension "d2287" distance P53 L43 = 7
  dimension "d2295" distance P61 P62 = 57
  dimension "d2296" diameter C12 = 4.25
  dimension "d2297" distance P65 L49 = 7
extrude "Extrude218" add sketch "Sketch60" profile of L1 L14 L45 L46 L47 L48 C12 L49 L50 L51 L52 L53 L54 to an object
extrude "Extrude215" cut sketch "Sketch60" profile of C8 C9 C10 C11 C12 to an object
extrude "Extrude216" cut sketch "Sketch60" profile of C8 L20 L21 L22 L23 L24 L25 L26 C9 L27 L28 L29 L30 L31 L32 C10 L33 L34 L35 L36 L37 L38 C11 L39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 against normal blind 6
chamfer "Chamfer25" distance 1.7
component_insert "Component Insert59"
joint "Assemble56" alignAngle 0 alignOffsetX 0 alignOffsetY 0 alignOffsetZ 0
component_insert "Component Insert60"
joint "Assemble57" alignAngle 0 alignOffsetX 0 alignOffsetY 0 alignOffsetZ 0
component_insert "Component Insert61"
joint "Assemble58" alignAngle 0 alignOffsetX 0 alignOffsetY 0 alignOffsetZ 0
